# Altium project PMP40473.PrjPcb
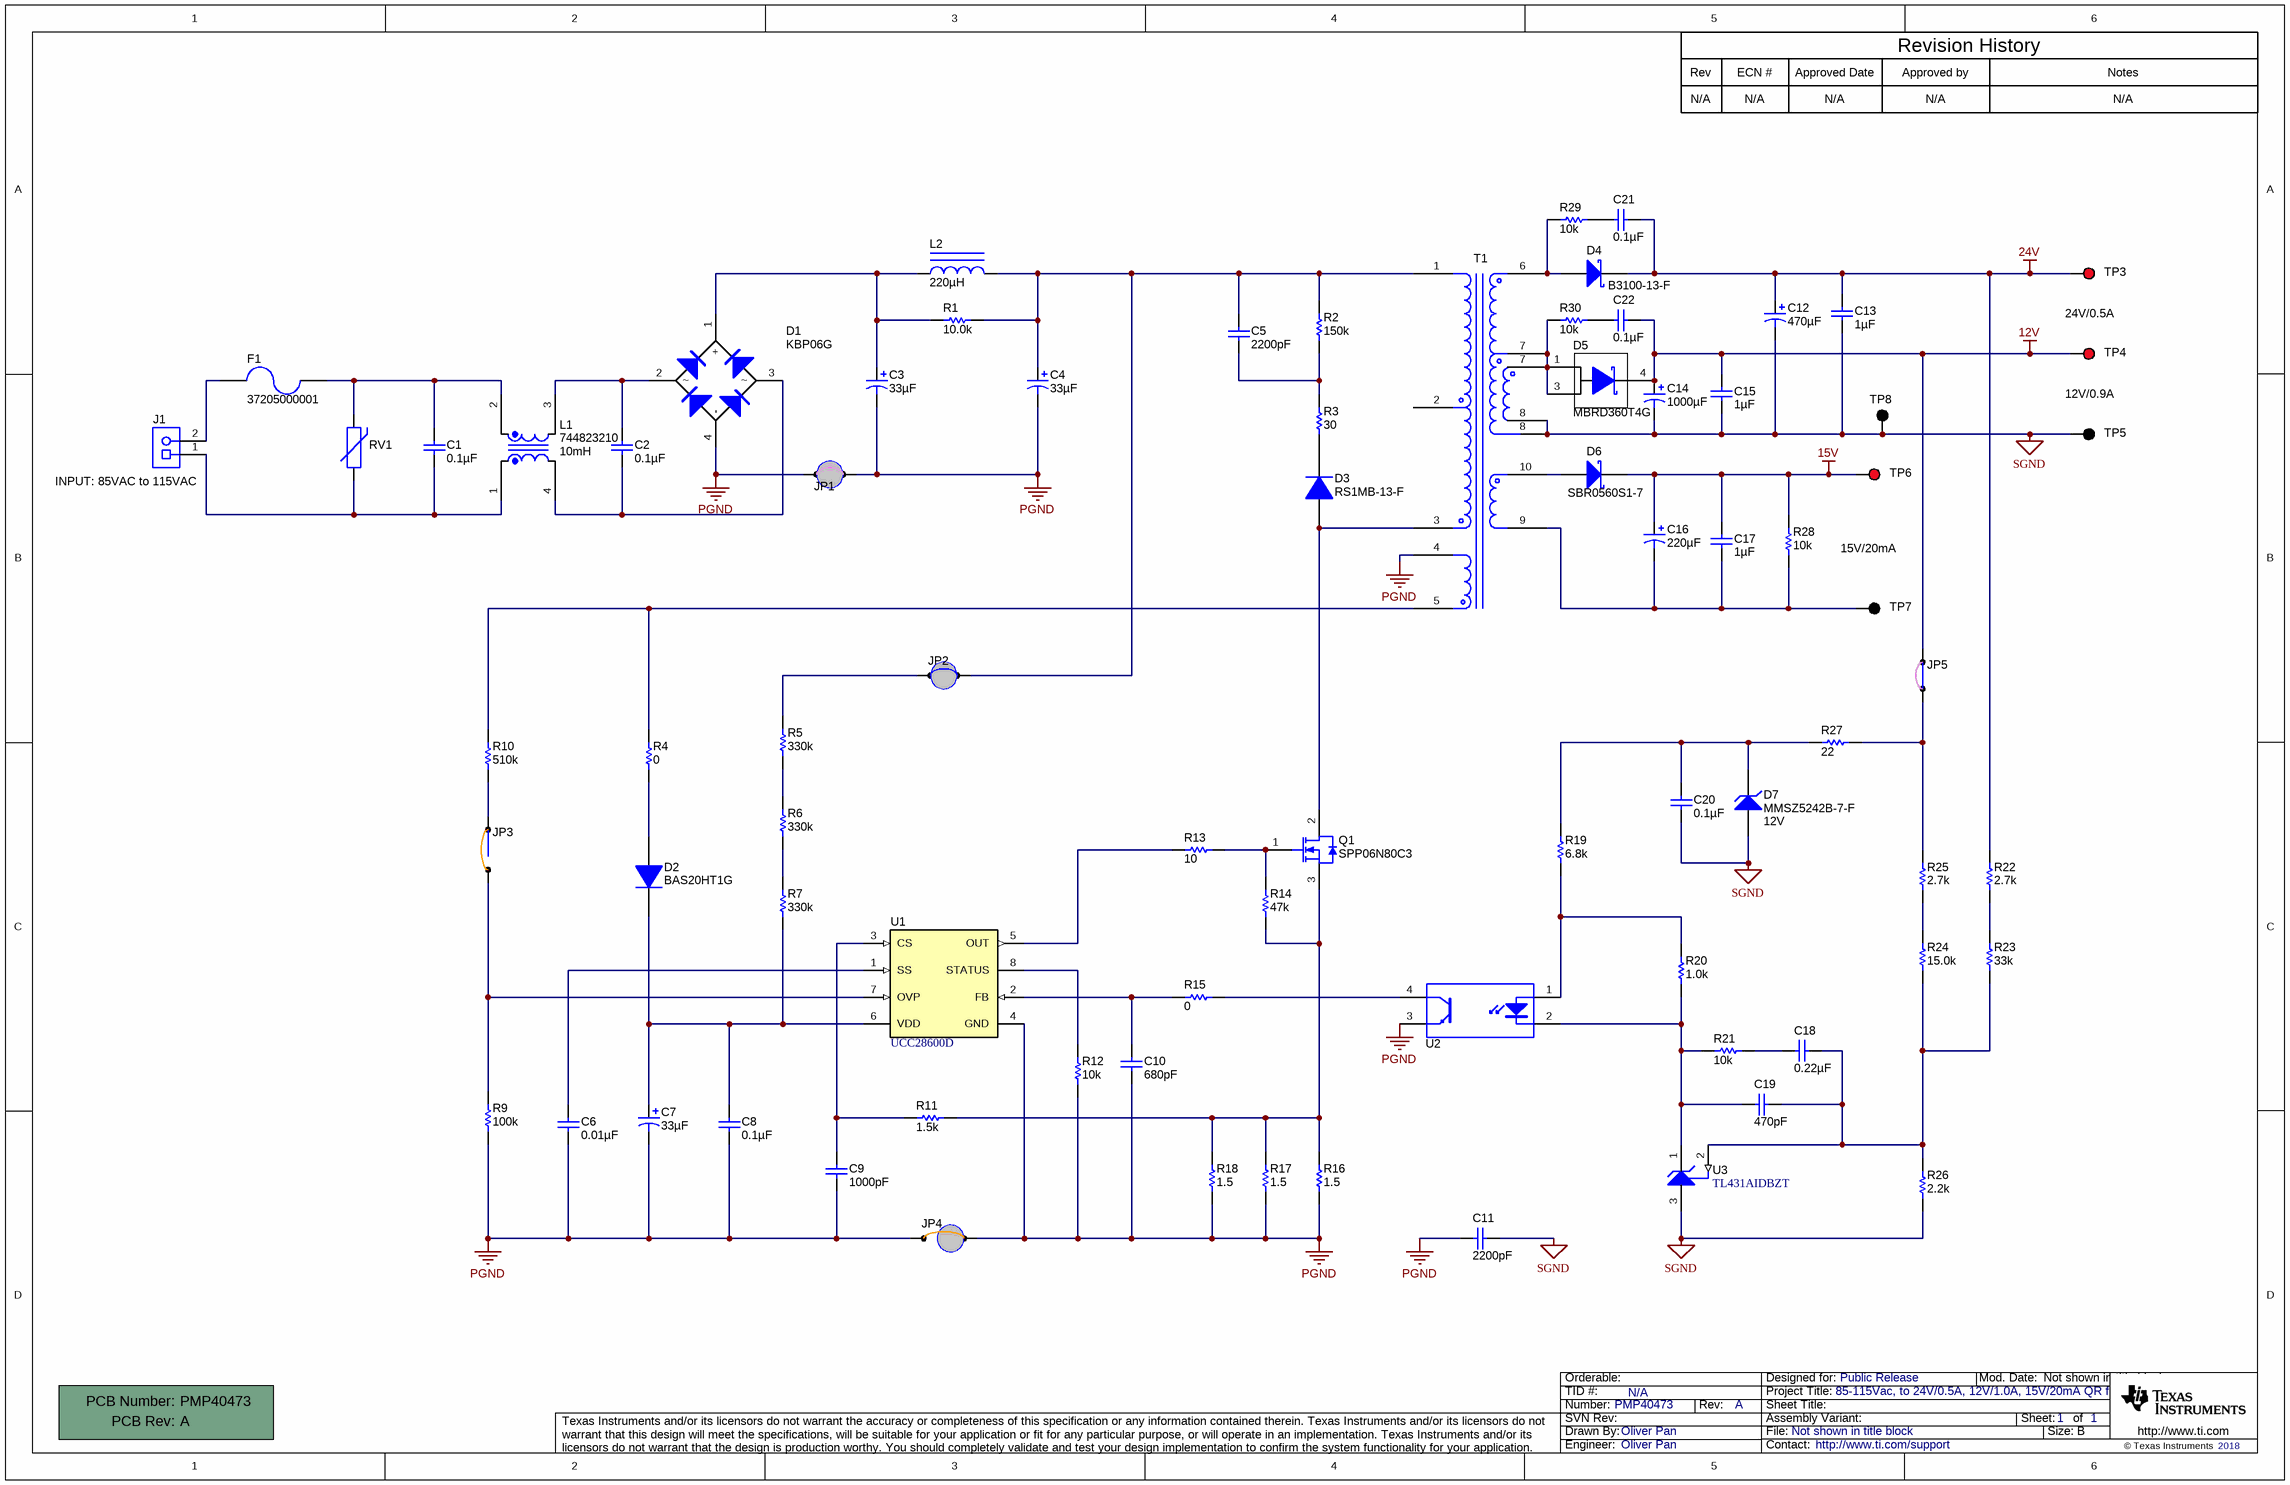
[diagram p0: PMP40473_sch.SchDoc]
CopyrightYear: 2018; PCB_Rev: A; PRJ_Customer: Public Release; PRJ_Engineer: Oliver Pan; PRJ_Number: PMP40473; PRJ_Title: 85-115Vac, to 24V/0.5A, 12V/1.0A, 15V/20mA QR flyback; SCH_Rev: A; TechSupport: http://www.ti.com/support; TID: N/A
1 sheet, 80 parts. Net scope: global (net labels, ports and power ports of the same name join across sheets).
Board file: PMP40473_pcb.PcbDoc

## Sheet PMP40473_sch.SchDoc
size 431 x 279 mm; Date: Not shown in title block; ApprovedBy: Not shown in title block; CheckedBy: Not shown in title block; Author: Not shown in title block; CompanyName: Not shown in title block; DrawnBy: Oliver Pan; Engineer: Not shown in title block; Organization: Not shown in title block; Address1: Not shown in title block; Address2: Not shown in title block; Address3: Not shown in title block; Address4: Not shown in title block; DocumentNumber: 1; Revision: Use project parameter SCH_Rev; SheetNumber: 1; SheetTotal: 1; PageSetup: Record=PageOptions¦CenterHorizontal=True¦CenterVertical=True¦PrintScale=1.00¦XCorrection=1.00¦YCorrection=1.00¦PrintKind=0¦BorderSize=5000000¦LeftOffset=0¦BottomOffset=0¦Orientation=2¦PaperLength=1000¦PaperWidth=1000¦Scale=100¦PaperSource=15¦PrintQuality=600¦MediaType=1¦DitherType=10¦PaperKind=Letter¦PrintScaleMode=1

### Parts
!PCB?  Printed Circuit Board  (value not drawn)  (mechanical)
C1  ValueDisplayed: 0.1µF  [WCAP-FTX2_1800x600x1200]  (hidden comment: 890324025017)
C2  ValueDisplayed: 0.1µF  [WCAP-FTX2_1800x600x1200]  (hidden comment: 890324025017)
C3  ValueDisplayed: 33µF  [KL_1000x2000]  (hidden comment: EKXG201ELL330MJ20S)
C4  ValueDisplayed: 33µF  [KL_1000x2000]  (hidden comment: EKXG201ELL330MJ20S)
C5  ValueDisplayed: 2200pF  [1206]  (hidden comment: GRM31BR72J222KW01L)
C6  ValueDisplayed: 0.01µF  [0805_HV]  (hidden comment: CC0805KRX7R9BB103)
C7  ValueDisplayed: 33µF  [Rubycon_500x1100]  (hidden comment: 35YXH33MEFC5X11)
C8  ValueDisplayed: 0.1µF  [0805_HV]  (hidden comment: C0805C104K5RACTU)
C9  ValueDisplayed: 1000pF  [0805_HV]  (hidden comment: GRM216R71E102KA01D)
C10  ValueDisplayed: 680pF  [0805_HV]  (hidden comment: GRM216R71E681KA01D)
C11  ValueDisplayed: 2200pF  [CAPRD1000W60D1000H1400]  (hidden comment: DE1E3KX222MA5BA01)
C12  ValueDisplayed: 470µF  [Chemi-Con_1000x2000]  (hidden comment: EKZE350ELL471MJ20S)
C13  ValueDisplayed: 1µF  [1206_180]  (hidden comment: C3216X7R1H105K160AB)
C14  ValueDisplayed: 1000µF  [Chemi-Con_1000x2000]  (hidden comment: EKMG250ELL102MJ20S)
C15  ValueDisplayed: 1µF  [1206]  (hidden comment: C1206C105K3RACTU)
C16  ValueDisplayed: 220µF  [Chemi-Con_800x1150]  (hidden comment: EKMG250ELL221MHB5D)
C17  ValueDisplayed: 1µF  [1206]  (hidden comment: C1206C105K3RACTU)
C18  ValueDisplayed: 0.22µF  [0805_HV]  (hidden comment: C2012X7R1H224K125AA)
C19  ValueDisplayed: 470pF  [0805_HV]  (hidden comment: 08055C471KAT2A)
C20  ValueDisplayed: 0.1µF  [0805_HV]  (hidden comment: GRM21BR71E104KA01L)
C21  ValueDisplayed: 0.1µF  [0805_HV]  (hidden comment: GRM21BR71E104KA01L)
C22  ValueDisplayed: 0.1µF  [0805_HV]  (hidden comment: GRM21BR71E104KA01L)
D1  KBP06G  [KBP]
D2  BAS20HT1G  [SOD-323]
D3  RS1MB-13-F  [SMB]
D4  B3100-13-F  [SMC]
D5  MBRD360T4G  [DPAK]
D6  SBR0560S1-7  [SOD-123]
D7  MMSZ5242B-7-F  value 12V  [SOD-123]
F1  37205000001  [FUSE_372]
J1  ED120/2DS  [On-Shore_ED120_2DS]  (value not drawn)
JP1  923345-20-C  [CONN_923345-07-C]  (value not drawn)
JP2  923345-20-C  [CONN_923345-06-C]  (value not drawn)
JP3  923345-20-C  [923345-03-C]  (value not drawn)
JP4  923345-20-C  [923345-03-C]  (value not drawn)
JP5  923345-20-C  [CONN_923345-07-C]  (value not drawn)
L1  744823210  ValueDisplayed: 10mH  [WE-CMB_M]
L2  ValueDisplayed: 220µH  [WE-TI_5075]  (hidden comment: Inductor Iron)
Q1  SPP06N80C3  [TO-220AB]
R1  ValueDisplayed: 10.0k  [0805_HV]  (hidden comment: Res2)
R2  ValueDisplayed: 150k  [CMF50]  (hidden comment: CMF50150K00FHEB)
R3  ValueDisplayed: 30  [1206]  (hidden comment: CRCW120630R0JNEA)
R4  ValueDisplayed: 0  [1206]  (hidden comment: RC1206JR-070RL)
R5  ValueDisplayed: 330k  [1206]  (hidden comment: CRCW1206330KJNEA)
R6  ValueDisplayed: 330k  [1206]  (hidden comment: CRCW1206330KJNEA)
R7  ValueDisplayed: 330k  [1206]  (hidden comment: CRCW1206330KJNEA)
R9  ValueDisplayed: 100k  [0805_HV]  (hidden comment: CRCW0805100KJNEA)
R10  ValueDisplayed: 510k  [0805_HV]  (hidden comment: CRCW0805510KJNEA)
R11  ValueDisplayed: 1.5k  [0805_HV]  (hidden comment: CRCW08051K50JNEA)
R12  ValueDisplayed: 10k  [0805_HV]  (hidden comment: CRCW080510K0JNEA)
R13  ValueDisplayed: 10  [0805_HV]  (hidden comment: CRCW080510R0JNEA)
R14  ValueDisplayed: 47k  [0805_HV]  (hidden comment: CRCW080547K0JNEA)
R15  ValueDisplayed: 0  [0805_HV]  (hidden comment: CRCW08050000Z0EA)
R16  ValueDisplayed: 1.5  [1206]  (hidden comment: CRCW12061R50JNEA)
R17  ValueDisplayed: 1.5  [1206]  (hidden comment: CRCW12061R50JNEA)
R18  ValueDisplayed: 1.5  [1206]  (hidden comment: CRCW12061R50JNEA)
R19  ValueDisplayed: 6.8k  [0805_HV]  (hidden comment: CRCW08056K80JNEA)
R20  ValueDisplayed: 1.0k  [0805_HV]  (hidden comment: CRCW08051K00JNEA)
R21  ValueDisplayed: 10k  [0805_HV]  (hidden comment: CRCW080510K0JNEA)
R22  ValueDisplayed: 2.7k  [0805_HV]  (hidden comment: CRCW08052K70JNEA)
R23  ValueDisplayed: 33k  [0805_HV]  (hidden comment: CRCW080533K0JNEA)
R24  ValueDisplayed: 15.0k  [0805_HV]  (hidden comment: CRCW080515K0FKEA)
R25  ValueDisplayed: 2.7k  [0805_HV]  (hidden comment: CRCW08052K70JNEA)
R26  ValueDisplayed: 2.2k  [0805_HV]  (hidden comment: CRCW08052K20JNEA)
R27  ValueDisplayed: 22  [1206]  (hidden comment: CRCW120622R0JNEA)
R28  ValueDisplayed: 10k  [1206]  (hidden comment: CRCW120610K0JNEA)
R29  ValueDisplayed: 10k  [1206]  (hidden comment: CRCW120610K0JNEA)
R30  ValueDisplayed: 10k  [1206]  (hidden comment: CRCW120610K0JNEA)
RV1  S10K275E2  [VAR_S10K275E2]  (value not drawn)
T1  750344218  [EE25-13-7_2607]  (value not drawn)
TP3  5010  [Keystone5010]  (value not drawn)
TP4  5010  [Keystone5010]  (value not drawn)
TP5  5011  [Keystone5011]  (value not drawn)
TP6  5010  [Keystone5010]  (value not drawn)
TP7  5011  [Keystone5011]  (value not drawn)
TP8  5011  [Keystone5011]  (value not drawn)
U1  UCC28600D  [D0008A_N]
U2  FOD817A  [DIP-4]  (value not drawn)
U3  TL431AIDBZT  [DBZ0003A_N]

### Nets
12V: C14.1(+) C15.1 C22.2 D5.4(K) JP5.2 TP4.1
15V: C16.1(+) C17.1 D6.1(K) R28.2 TP6.1
24V: C12.1(+) C13.1 C21.2 D4.1(K) R22.2 TP3.1
PGND: C3.2(-) C4.2(-) C6.1 C7.2(-) C8.2 C9.2 C10.2 C11.1 D1.4(-) JP1.1 JP1.2 JP4.1 JP4.2 R9.1 R12.1 R16.1 R17.1 R18.1 T1.4 U1.4(GND) U2.3(E)
SGND: C11.2 C12.2(-) C13.2 C14.2(-) C15.2 C20.2 D7.2(A) R26.1 T1.8 TP5.1 TP8.1 U3.3(ANODE)
NetC1_1: C1.1 F1.2 L1.2 RV1.2
NetC1_2: C1.2 J1.1 L1.1 RV1.1
NetC2_1: C2.1 D1.2 L1.3
NetC2_2: C2.2 D1.3 L1.4
NetC3_1: C3.1(+) D1.1(+) L2.1 R1.1
NetC4_1: C4.1(+) C5.1 JP2.2 L2.2 R1.2 R2.2 T1.1
NetC5_2: C5.2 R2.1 R3.2
NetC6_2: C6.2 U1.1(SS)
NetC7_1: C7.1(+) C8.1 D2.1(K) R7.1 U1.6(VDD)
NetC9_1: C9.1 R11.1 U1.3(CS)
NetC10_1: C10.1 R15.2 U1.2(FB)
NetC16_2: C16.2(-) C17.2 R28.1 T1.9 TP7.1
NetC18_1: C18.1 C19.1 R23.1 R24.1 R26.2 U3.2(REF)
NetC18_2: C18.2 R21.1
NetC19_2: C19.2 R20.2 R21.2 U2.2(K) U3.1(CATHODE)
NetC20_1: C20.1 D7.1(K) R19.1 R27.2
NetC21_1: C21.1 R29.1
NetC22_1: C22.1 R30.1
NetD2_2: D2.2(A) R4.1
NetD3_1: D3.1(K) R3.1
NetD3_2: D3.2(A) Q1.2(D) T1.3
NetD4_2: D4.2(A) R29.2 T1.6
NetD5_1: D5.1(A) D5.3(A) R30.2 T1.7
NetD6_2: D6.2(A) T1.10
NetF1_1: F1.1 J1.2
NetJP2_1: JP2.1 R5.2
NetJP3_1: JP3.1 R9.2 U1.7(OVP)
NetJP3_2: JP3.2 R10.1
NetJP5_1: JP5.1 R25.2 R27.1
NetQ1_1: Q1.1(G) R13.1 R14.2
NetQ1_3: Q1.3(S) R11.2 R14.1 R16.2 R17.2 R18.2
NetR4_2: R4.2 R10.2 T1.5
NetR5_1: R5.1 R6.2
NetR6_1: R6.1 R7.2
NetR12_2: R12.2 U1.8(STATUS)
NetR13_2: R13.2 U1.5(OUT)
NetR15_1: R15.1 U2.4(C)
NetR19_2: R19.2 R20.1 U2.1(A)
NetR22_1: R22.1 R23.2
NetR24_2: R24.2 R25.1

Not connected (* = marked no-connect by the designer): T1 2

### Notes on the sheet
- Rev
- N/A
- ECN #
- Approved Date
- Approved by
- Revision History
- Notes
- 24V/0.5A
- 12V/0.9A
- (near J1) INPUT: 85VAC to 115VAC
- 15V/20mA

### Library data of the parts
!PCB? = PCB: Manufacturer: Any; PartNumber: PMP40473; SymbolCreator: a0412235
C1 C2 = 890324025017: CAP, Film, 0.1 µF, X2 275 VAC, +/- 10%, TH; Manufacturer: Wurth Elektronik; Polarized: N; CompType: Capacitor; Value: 0.1uF; U/M: EA; Cap_F: 0.0000001; Tolerance_%: 10; TaMin_C: -40; TaMax_C: 105; Cap_Case: 18x6x12mm; AEC Category: Q200; Green_Lifecycle: Not Set; Green_REACh: Incomplete; VAC_X: 275
C3 C4 = EKXG401EC3330ML20S: CAP, AL, 33 µF, 400 V, +/- 20%, TH; Manufacturer: Chemi-Con; Polarized: Y; CompType: Capacitor; Value: 33uF; U/M: EA; Cap_F: 0.000033; Tolerance_%: 20; VDC_V: 200; Value2: 200V; IRMS_A: 0.26; TaMin_C: -40; TaMax_C: 105; Cap_Case: 10x20mm; SizeAreaWB_mm2: 324; SizeArea_mm2: 256; SizeX_mm: 10; SizeZ_mm: 21.5; AEC Category: Q200; AEC Qualified: N
C5 = GRM31BR72J222KW01L: CAP, CERM, 2200 pF, 630 V,+/- 10%, X7R, 1206; Manufacturer: MuRata; Polarized: N; CompType: Capacitor; Value: 2200pF; U/M: EA; Cap_F: 0.0000000022; Tolerance_%: 10; VDC_V: 630; Value2: 630V; TaMin_C: -55; TaMax_C: 125; SizeArea_mm2: 5.12; SizeAreaWB_mm2: 10.92; SizeX_mm: 3.2; SizeY_mm: 1.6; SizeZ_mm: 1.35; AEC Category: Q200; Green_Lifecycle: Not Set; Green_REACh: Incomplete
C6 = CC0805KRX7R9BB103: CAP, CERM, 0.01 µF, 50 V,+/- 10%, X7R, 0805; Manufacturer: Yageo America; Polarized: N; CompType: Capacitor; Value: 0.01uF; U/M: EA; Cap_F: 0.00000001; Tolerance_%: 10; VDC_V: 50; Value2: 50V; TaMin_C: -55; TaMax_C: 125; Cap_Case: 0805; SizeArea_mm2: 2.5; SizeAreaWB_mm2: 6.75; SizeX_mm: 2; SizeY_mm: 1.25; SizeZ_mm: 1.45; AEC Category: Q200; Green_Lifecycle: Active; Green_REACh: Passed
C7 = 35YXH33MEFC5X11: CAP, AL, 33 µF, 35 V, +/- 20%, TH; Manufacturer: Rubycon; Polarized: Y; CompType: Capacitor; Value: 33uF; U/M: EA; Cap_F: 0.000033; Tolerance_%: 20; VDC_V: 35; Value2: 35V; IRMS_A: 0.21; TaMin_C: -40; TaMax_C: 105; Cap_Case: 5x11mm; SizeAreaWB_mm2: 49; SizeArea_mm2: 25; SizeX_mm: 5; SizeZ_mm: 12.5; AEC Category: Q200; AEC Qualified: N
C8 = C0805C104K5RACTU: CAP, CERM, 0.1 µF, 50 V,+/- 10%, X7R, 0805; Manufacturer: Kemet; Polarized: N; CompType: Capacitor; Value: 0.1uF; U/M: EA; Cap_F: 0.0000001; Tolerance_%: 10; ESR_ohm: 0.064; Value1: 0.064 ohm; VDC_V: 50; Value2: 50V; IRMS_A: 1.64; TaMin_C: -55; TaMax_C: 125; Cap_Case: 0805; SizeArea_mm2: 2.5; SizeAreaWB_mm2: 6.75; SizeX_mm: 2; SizeY_mm: 1.25; SizeZ_mm: 1.45; AEC Category: Q200; Green_Lifecycle: Active; Green_REACh: Passed
C9 = GRM216R71E102KA01D: CAP, CERM, 1000 pF, 25 V,+/- 10%, X7R, 0805; Manufacturer: MuRata; Polarized: N; CompType: Capacitor; Value: 1000pF; U/M: EA; Cap_F: 0.000000001; Tolerance_%: 10; VDC_V: 25; Value2: 25V; TaMin_C: -55; TaMax_C: 125; Cap_Case: 0805; SizeArea_mm2: 2.5; SizeAreaWB_mm2: 6.75; SizeX_mm: 2; SizeY_mm: 1.25; SizeZ_mm: 1.45; AEC Category: Q200; Green_Lifecycle: Active; Green_REACh: Passed
C10 = GRM216R71E681KA01D: CAP, CERM, 680 pF, 25 V,+/- 10%, X7R, 0805; Manufacturer: MuRata; Polarized: N; CompType: Capacitor; Value: 680pF; U/M: EA; Cap_F: 0.00000000068; Tolerance_%: 10; VDC_V: 25; Value2: 25V; TaMin_C: -55; TaMax_C: 125; Cap_Case: 0805; SizeArea_mm2: 2.5; SizeAreaWB_mm2: 6.75; SizeX_mm: 2; SizeY_mm: 1.25; SizeZ_mm: 1.45; AEC Category: Q200
C11 = DE1E3KX222MA5BA01: CAP, CERM, 2200 pF, 250 V, +/- 20%, E, Disc 10x8mm; Manufacturer: MuRata; Polarized: N; CompType: Capacitor; Value: 2200pF; U/M: EA; Cap_F: 0.0000000022; Tolerance_%: 20; Value1: Unknown; VDC_V: 250; Value2: 250V; TaMin_C: -25; TaMax_C: 85; SizeArea_mm2: 80; SizeAreaWB_mm2: 120; SizeX_mm: 10; SizeY_mm: 8; SizeZ_mm: 14; AEC Category: Q200
C12 = EKZE350ELL471MJ20S: CAP, AL, 470 µF, 35 V, +/- 20%, TH; Manufacturer: Chemi-Con; Polarized: Y; CompType: Capacitor; Value: 470uF; U/M: EA; Cap_F: 0.00047; Tolerance_%: 20; VDC_V: 35; Value2: 35V; IRMS_A: 1.82; TaMin_C: -40; TaMax_C: 105; Cap_Case: 10x20; SizeAreaWB_mm2: 144; SizeArea_mm2: 100; SizeX_mm: 10; SizeZ_mm: 21.5; AEC Category: Q200; AEC Qualified: N
C13 = C3216X7R1H105K160AB: CAP, CERM, 1 µF, 50 V,+/- 10%, X7R, 1206; Manufacturer: TDK; Polarized: N; CompType: Capacitor; Value: 1uF; U/M: EA; Cap_F: 0.000001; Tolerance_%: 10; ESR_ohm: 0.009289; Value1: 0.009289 ohm; VDC_V: 50; Value2: 50V; IRMS_A: 2.38446; TaMin_C: -55; TaMax_C: 125; Cap_Case: 1206; SizeArea_mm2: 5.12; SizeAreaWB_mm2: 10.92; SizeX_mm: 3.2; SizeY_mm: 1.6; SizeZ_mm: 1.8; AEC Category: Q200; Green_Lifecycle: NRND; Green_REACh: Passed
C14 = EKMG250ELL102MJ20S: CAP, AL, 1000 µF, 25 V, +/- 20%, TH; Manufacturer: Chemi-Con; Polarized: Y; CompType: Capacitor; Value: 1000uF; U/M: EA; Cap_F: 0.001; Tolerance_%: 20; VDC_V: 25; Value2: 25V; IRMS_A: 0.68; TaMin_C: -55; TaMax_C: 105; Cap_Case: 10x20mm; SizeAreaWB_mm2: 144; SizeArea_mm2: 100; SizeX_mm: 10; SizeZ_mm: 21.5; AEC Category: Q200; AEC Qualified: N
C15 C17 = C1206C105K3RACTU: CAP, CERM, 1 µF, 25 V,+/- 10%, X7R, 1206; Manufacturer: Kemet; Polarized: N; CompType: Capacitor; Value: 1uF; U/M: EA; Cap_F: 0.000001; Tolerance_%: 10; ESR_ohm: 0.011; Value1: 0.011 ohm; VDC_V: 25; Value2: 25V; IRMS_A: 3.55; TaMin_C: -55; TaMax_C: 125; SizeArea_mm2: 5.12; SizeAreaWB_mm2: 10.92; SizeX_mm: 3.2; SizeY_mm: 1.6; SizeZ_mm: 1.35; AEC Category: Q200; Green_Lifecycle: Active; Green_REACh: Passed
C16 = EKMG250ELL221MHB5D: CAP, AL, 220 µF, 25 V, +/- 20%, TH; Manufacturer: Chemi-Con; Polarized: Y; CompType: Capacitor; Value: 220uF; U/M: EA; Cap_F: 0.00022; Tolerance_%: 20; VDC_V: 25; Value2: 25V; IRMS_A: 0.23; TaMin_C: -55; TaMax_C: 105; Cap_Case: 8x11.5mm; SizeAreaWB_mm2: 100; SizeArea_mm2: 64; SizeX_mm: 8; SizeZ_mm: 13; AEC Category: Q200; AEC Qualified: N
C18 = C2012X7R1H224K125AA: CAP, CERM, 0.22 µF, 50 V,+/- 10%, X7R, 0805; Manufacturer: TDK; Polarized: N; CompType: Capacitor; Value: 0.22uF; U/M: EA; Cap_F: 0.00000022; Tolerance_%: 10; ESR_ohm: 0.016949; Value1: 0.016949 ohm; VDC_V: 50; Value2: 50V; IRMS_A: 1.59611; TaMin_C: -55; TaMax_C: 125; Cap_Case: 0805; SizeArea_mm2: 2.5; SizeAreaWB_mm2: 6.75; SizeX_mm: 2; SizeY_mm: 1.25; SizeZ_mm: 1.45; AEC Category: Q200; Green_Lifecycle: Active; Green_REACh: Passed
C19 = 08055C471KAT2A: CAP, CERM, 470 pF, 50 V,+/- 10%, X7R, 0805; Manufacturer: AVX; Polarized: N; CompType: Capacitor; Value: 470pF; U/M: EA; Cap_F: 0.00000000047; Tolerance_%: 10; ESR_ohm: 0.454; Value1: 0.454 ohm; VDC_V: 50; Value2: 50V; TaMin_C: -55; TaMax_C: 125; Cap_Case: 0805; SizeArea_mm2: 2.5; SizeAreaWB_mm2: 6.75; SizeX_mm: 2; SizeY_mm: 1.25; SizeZ_mm: 1.45; AEC Category: Q200; Green_Lifecycle: Not Set; Green_REACh: Incomplete
C20-C22 = GRM21BR71E104KA01L: CAP, CERM, 0.1 µF, 25 V,+/- 10%, X7R, 0805; Manufacturer: MuRata; Polarized: N; CompType: Capacitor; Value: 0.1uF; U/M: EA; Cap_F: 0.0000001; Tolerance_%: 10; VDC_V: 25; Value2: 25V; TaMin_C: -55; TaMax_C: 125; Cap_Case: 0805; SizeArea_mm2: 2.5; SizeAreaWB_mm2: 6.75; SizeX_mm: 2; SizeY_mm: 1.25; SizeZ_mm: 1.45; AEC Category: Q200; Green_Lifecycle: Active; Green_REACh: Passed
D1 = KBP06G: Diode, Switching-Bridge, 600 V, 1.5 A, TH; Manufacturer: Diodes Inc.; U/M: EA; Vf_V: 1.1; Value: 600V; Value1: 1.5A; Value2: 1.1V; Io_A: 1.5; Vr_V: 600; TJmax_C: 150; RJC_CperW: 18; SizeAreaWB_mm2: 79.75; SizeArea_mm2: 43.75; SizeX_mm: 12.5; SizeY_mm: 3.5; SizeZ_mm: 12.69; AEC Category: Q101; Green_Lifecycle: Not Set; Green_REACh: Incomplete
D2 = BAS20HT1G: Diode, Switching, 200 V, 0.2 A, AEC-Q101, SOD-323; Manufacturer: ON Semiconductor; U/M: EA; Vf_V: 1.25; Value: 200V; Value1: 0.2A; Value2: 1.25V; Io_A: 0.2; Vr_V: 200; TJmax_C: 150; SizeAreaWB_mm2: 8.695; SizeArea_mm2: 3.645; SizeX_mm: 2.7; SizeY_mm: 1.35; SizeZ_mm: 1; AEC Category: Q101; AEC Qualified: Y
D3 = RS1MB-13-F: Diode, P-N, 1000 V, 1 A, SMB; Manufacturer: Diodes Inc.; U/M: EA; Vf_V: 1.3; Value: 1000V; Value1: 1A; Value2: 1.3V; Io_A: 1; Vr_V: 1000; TJmax_C: 150; RJC_CperW: 20; SizeAreaWB_mm2: 44.156; SizeArea_mm2: 21.336; SizeX_mm: 5.6; SizeY_mm: 3.81; SizeZ_mm: 2.6; AEC Category: Q101; Green_Lifecycle: Active; Green_REACh: Passed
D4 = B3100-13-F: Diode, Schottky, 100 V, 3 A, SMC; Manufacturer: Diodes Inc.; U/M: EA; Vf_V: 0.79; Value: 100V; Value1: 3A; Value2: 0.79V; Io_A: 3; Vr_V: 100; TJmax_C: 125; RJC_CperW: 10; SizeAreaWB_mm2: 83.2686; SizeArea_mm2: 50.5686; SizeX_mm: 8.13; SizeY_mm: 6.22; SizeZ_mm: 2.6; AEC Category: Q101; Green_Lifecycle: Active; Green_REACh: Passed
D5 = MBRD360T4G: Diode, Schottky, 60 V, 3 A, DPAK; Manufacturer: ON Semiconductor; U/M: EA; Vf_V: 0.6; Value: 60V; Value1: 3A; Value2: 0.6V; Io_A: 3; Vr_V: 60; TJmax_C: 150; RJC_CperW: 6; SizeAreaWB_mm2: 101.7114; SizeArea_mm2: 64.8114; SizeX_mm: 9.91; SizeY_mm: 6.54; SizeZ_mm: 2.29; AEC Category: Q101; Green_Lifecycle: Not Set; Green_REACh: Incomplete
D6 = SBR0560S1-7: Diode, Schottky, 60 V, 0.5 A, SOD-123; Manufacturer: Diodes Inc.; U/M: EA; Vf_V: 0.5; Value: 60V; Value1: 0.5A; Value2: 0.5V; Vr_V: 60; TJmax_C: 150; SizeAreaWB_mm2: 13.095; SizeArea_mm2: 6.545; SizeX_mm: 3.85; SizeY_mm: 1.7; SizeZ_mm: 1.35; AEC Category: Q101; AEC Qualified: N; Green_Lifecycle: Not Set; Green_REACh: Incomplete
D7 = MMSZ5242B-7-F: Diode, Zener, 12 V, 500 mW, SOD-123; Manufacturer: Diodes Inc.; U/M: EA; Value1: 0.5W; SizeAreaWB_mm2: 13.095; SizeArea_mm2: 6.545; SizeX_mm: 3.85; SizeY_mm: 1.7; SizeZ_mm: 1.35; AEC Category: Q101; SymbolCreator: a0412235; Power_W: 0.5; Vz_V: 12; RJA_CperW: 350
F1 = 37205000001: Fuse, 0.5 A, 250VAC/VDC, TH; Manufacturer: Littelfuse; VDC_V: 250; Irating_A: 0.5
J1 = CMP-0074910-1: Terminal Block, 5.08 mm, 2x1, Brass, TH; Manufacturer: On-Shore Technology; Cert_VDE: Y; CNHeader: False; Current_A: 15A; Green_Lifecycle: Not Set; Shrouded: N; Gender: Female; Green_REACh: Incomplete; Voltage_V: 300V; Row_Count: 1; Pitch_mm: 5.08; CT: True
JP1 JP5 = CMP-0074936-1: Jumper Wire, 700mil spacing, Violet, pkg of 150, TH; Manufacturer: 3M; CNHeader: False; Green_Lifecycle: Active; Green_REACh: Passed
JP2 = CMP-0074937-1: Jumper Wire, 600mil spacing, Blue, pkg of 150, TH; Manufacturer: 3M; CNHeader: False; Green_Lifecycle: Active; Green_REACh: Passed
JP3 JP4 = CMP-0055440-1: Jumper Wire, 300mil spacing, Orange, pkg of 200; Manufacturer: 3M; CNHeader: FALSE; Green_Lifecycle: Active; Green_REACh: Passed
L1 = 744823210: Coupled inductor, 10 mH, 2 A, 0.125 ohm, TH; Manufacturer: Wurth Elektronik; SymbolCreator: a0799628; SizeAreaWB_mm2: 513; SizeArea_mm2: 425; SizeX_mm: 25; SizeY_mm: 17; SizeZ_mm: 26.5; Value: 10mH; Ind_H: 10.0E-3; DCR_ohm: 0.125; AEC Category: Q200
L2 = 7447462221: Inductor, Unshielded Drum Core, Ferrite, 220 µH, 0.5 A, 0.96 ohm, TH; Manufacturer: Wurth Elektronik; Value: 220uH; Ind_H: 220.0E-6; Imax_A: 0.5; Irms: 0.5A @ 40C rise; Isat: 0.5A @ 10% inductance drop; DCR_ohm: 0.96; Value2: 0.5A; AEC Category: Q200
Q1 = SPP06N80C3: MOSFET, N-CH, 800 V, 6 A, TO-220AB; Manufacturer: Infineon Technologies; Alternate Manufacturer: None; U/M: EA; ChType: N; Value: 800V; VdsMax_V: 800; Value1: 0.9 ohm; Rdson45_ohm: 0.9; Value2: 41 nC; QgTyp_nC: 41; Vgs_V: 3.9; IdsMax_A: 6; SizeAreaWB_mm2: 79.3; SizeArea_mm2: 45.9; SizeX_mm: 10.2; SizeY_mm: 4.5; SizeZ_mm: 19.4; AEC Category: Q101; Green_Lifecycle: Not Set; Green_REACh: Incomplete
R1 = CRCW080510K0FKEA: RES, 10.0 k, 1%, 0.125 W, 0805; Manufacturer: Vishay-Dale; CompType: Resistor; Value: 10.0k; Res_ohm: 10000; Value_Code: 10k0; Tolerance_%: 1; Power_W: 0.125; Value2: 0.125W; VDC_V: 150; TempCo: 100 ppm/C; EIA_Code: E96; U/M: EA; AEC Category: Q200
R2 = CMF50150K00FHEB: RES, 150 k, 1%, 0.25 W, Axial; Manufacturer: Vishay-Dale; CompType: Resistor; Value: 150k; Res_ohm: 150000; Tolerance_%: 1; Power_W: 0.25; Value2: 0.25W; VDC_V: 200; TempCo: 50 ppm/C; EIA_Code: E96; U/M: EA; AEC Category: Q200
R3 = CRCW120630R0JNEA: RES, 30, 5%, 0.25 W, 1206; Manufacturer: Vishay-Dale; CompType: Resistor; Value: 30; Value_Code: 30R0; Tolerance_%: 5; Power_W: 0.25; Value2: 0.25W; VDC_V: 200; TempCo: 200 ppm/C; EIA_Code: E24; U/M: EA; SizeArea_mm2: 5.12; SizeX_mm: 3.2; SizeY_mm: 1.6; SizeZ_mm: 1.35; AEC Category: Q200
R4 = RC1206JR-070RL: RES, 0, 5%, 0.25 W, 1206; Manufacturer: Yageo America; CompType: Resistor; Value: 0; Value_Code: 0000; Tolerance_%: 5; Power_W: 0.25; Value2: 0.25W; VDC_V: 200; TempCo: 200 ppm/C; SizeArea_mm2: 5.12; SizeX_mm: 3.2; SizeY_mm: 1.6; SizeZ_mm: 1.35; EIA_Code: E24; U/M: EA; AEC Category: Q200; Green_Lifecycle: Active; Green_REACh: Passed
R5-R7 = CRCW1206330KJNEA: RES, 330 k, 5%, 0.25 W, 1206; Manufacturer: Vishay-Dale; CompType: Resistor; Value: 330k; Res_ohm: 330000; Tolerance_%: 5; Power_W: 0.25; Value2: 0.25W; VDC_V: 200; TempCo: 200 ppm/C; SizeArea_mm2: 5.12; SizeX_mm: 3.2; SizeY_mm: 1.6; SizeZ_mm: 1.35; EIA_Code: E24; U/M: EA; AEC Category: Q200
R9 = CRCW0805100KJNEA: RES, 100 k, 5%, 0.125 W, 0805; Manufacturer: Vishay-Dale; CompType: Resistor; Value: 100k; Res_ohm: 100000; Tolerance_%: 5; Power_W: 0.125; Value2: 0.125W; VDC_V: 150; TempCo: 200 ppm/C; SizeArea_mm2: 2.5; SizeX_mm: 2; SizeY_mm: 1.25; SizeZ_mm: 1.45; EIA_Code: E24; U/M: EA; AEC Category: Q200; Green_Lifecycle: Active; Green_REACh: Passed
R10 = CRCW0805510KJNEA: RES, 510 k, 5%, 0.125 W, 0805; Manufacturer: Vishay-Dale; CompType: Resistor; Value: 510k; Res_ohm: 510000; Tolerance_%: 5; Power_W: 0.125; Value2: 0.125W; VDC_V: 150; TempCo: 200 ppm/C; SizeArea_mm2: 2.5; SizeX_mm: 2; SizeY_mm: 1.25; SizeZ_mm: 1.45; EIA_Code: E24; U/M: EA; AEC Category: Q200; Green_Lifecycle: Active; Green_REACh: Passed
R11 = CRCW08051K50JNEA: RES, 1.5 k, 5%, 0.125 W, 0805; Manufacturer: Vishay-Dale; CompType: Resistor; Value: 1.5k; Res_ohm: 1500; Value_Code: 1k50; Tolerance_%: 5; Power_W: 0.125; Value2: 0.125W; VDC_V: 150; TempCo: 200 ppm/C; SizeArea_mm2: 2.5; SizeX_mm: 2; SizeY_mm: 1.25; SizeZ_mm: 1.45; EIA_Code: E24; U/M: EA; AEC Category: Q200
R12 R21 = CRCW080510K0JNEA: RES, 10 k, 5%, 0.125 W, 0805; Manufacturer: Vishay-Dale; CompType: Resistor; Value: 10k; Res_ohm: 10000; Value_Code: 10k0; Tolerance_%: 5; Power_W: 0.125; Value2: 0.125W; VDC_V: 150; TempCo: 200 ppm/C; SizeArea_mm2: 2.5; SizeX_mm: 2; SizeY_mm: 1.25; SizeZ_mm: 1.45; EIA_Code: E24; U/M: EA; AEC Category: Q200; Green_Lifecycle: Active; Green_REACh: Passed
R13 = CRCW080510R0JNEA: RES, 10, 5%, 0.125 W, 0805; Manufacturer: Vishay-Dale; CompType: Resistor; Value: 10; Value_Code: 10R0; Tolerance_%: 5; Power_W: 0.125; Value2: 0.125W; VDC_V: 150; TempCo: 200 ppm/C; SizeArea_mm2: 2.5; SizeX_mm: 2; SizeY_mm: 1.25; SizeZ_mm: 1.45; EIA_Code: E24; U/M: EA; AEC Category: Q200
R14 = CRCW080547K0JNEA: RES, 47 k, 5%, 0.125 W, 0805; Manufacturer: Vishay-Dale; CompType: Resistor; Value: 47k; Res_ohm: 47000; Value_Code: 47k0; Tolerance_%: 5; Power_W: 0.125; Value2: 0.125W; VDC_V: 150; TempCo: 200 ppm/C; SizeArea_mm2: 2.5; SizeX_mm: 2; SizeY_mm: 1.25; SizeZ_mm: 1.45; EIA_Code: E24; U/M: EA; AEC Category: Q200
R15 = CRCW08050000Z0EA: RES, 0, 5%, 0.125 W, 0805; Manufacturer: Vishay-Dale; CompType: Resistor; Value: 0; Value_Code: 0000; Tolerance_%: 5; Power_W: 0.125; Value2: 0.125W; VDC_V: 150; TempCo: 200 ppm/C; SizeArea_mm2: 2.5; SizeX_mm: 2; SizeY_mm: 1.25; SizeZ_mm: 1.45; EIA_Code: E24; U/M: EA; AEC Category: Q200; Green_Lifecycle: Active; Green_REACh: Passed
R16-R18 = CRCW12061R50JNEA: RES, 1.5, 5%, 0.25 W, 1206; Manufacturer: Vishay-Dale; CompType: Resistor; Value: 1.5; Value_Code: 1R50; Tolerance_%: 5; Power_W: 0.25; Value2: 0.25W; VDC_V: 200; TempCo: 200 ppm/C; SizeArea_mm2: 5.12; SizeX_mm: 3.2; SizeY_mm: 1.6; SizeZ_mm: 1.35; EIA_Code: E24; U/M: EA; AEC Category: Q200
R19 = CRCW08056K80JNEA: RES, 6.8 k, 5%, 0.125 W, 0805; Manufacturer: Vishay-Dale; CompType: Resistor; Value: 6.8k; Res_ohm: 6800; Value_Code: 6k80; Tolerance_%: 5; Power_W: 0.125; Value2: 0.125W; VDC_V: 150; TempCo: 200 ppm/C; SizeArea_mm2: 2.5; SizeX_mm: 2; SizeY_mm: 1.25; SizeZ_mm: 1.45; EIA_Code: E24; U/M: EA; AEC Category: Q200
R20 = CRCW08051K00JNEA: RES, 1.0 k, 5%, 0.125 W, 0805; Manufacturer: Vishay-Dale; CompType: Resistor; Value: 1.0k; Res_ohm: 1000; Value_Code: 1k00; Tolerance_%: 5; Power_W: 0.125; Value2: 0.125W; VDC_V: 150; TempCo: 200 ppm/C; SizeArea_mm2: 2.5; SizeX_mm: 2; SizeY_mm: 1.25; SizeZ_mm: 1.45; EIA_Code: E24; U/M: EA; AEC Category: Q200; Green_Lifecycle: Active; Green_REACh: Passed
R22 R25 = CRCW08052K70JNEA: RES, 2.7 k, 5%, 0.125 W, 0805; Manufacturer: Vishay-Dale; CompType: Resistor; Value: 2.7k; Res_ohm: 2700; Value_Code: 2k70; Tolerance_%: 5; Power_W: 0.125; Value2: 0.125W; VDC_V: 150; TempCo: 200 ppm/C; SizeArea_mm2: 2.5; SizeX_mm: 2; SizeY_mm: 1.25; SizeZ_mm: 1.45; EIA_Code: E24; U/M: EA; AEC Category: Q200
R23 = CRCW080533K0JNEA: RES, 33 k, 5%, 0.125 W, 0805; Manufacturer: Vishay-Dale; CompType: Resistor; Value: 33k; Res_ohm: 33000; Value_Code: 33k0; Tolerance_%: 5; Power_W: 0.125; Value2: 0.125W; VDC_V: 150; TempCo: 200 ppm/C; SizeArea_mm2: 2.5; SizeX_mm: 2; SizeY_mm: 1.25; SizeZ_mm: 1.45; EIA_Code: E24; U/M: EA; AEC Category: Q200
R24 = CRCW080515K0FKEA: RES, 15.0 k, 1%, 0.125 W, 0805; Manufacturer: Vishay-Dale; CompType: Resistor; Value: 15.0k; Res_ohm: 15000; Value_Code: 15k0; Tolerance_%: 1; Power_W: 0.125; Value2: 0.125W; VDC_V: 150; TempCo: 100 ppm/C; SizeArea_mm2: 2.5; SizeX_mm: 2; SizeY_mm: 1.25; SizeZ_mm: 1.45; EIA_Code: E96; U/M: EA; AEC Category: Q200; Green_Lifecycle: Active; Green_REACh: Passed
R26 = CRCW08052K20JNEA: RES, 2.2 k, 5%, 0.125 W, 0805; Manufacturer: Vishay-Dale; CompType: Resistor; Value: 2.2k; Res_ohm: 2200; Value_Code: 2k20; Tolerance_%: 5; Power_W: 0.125; Value2: 0.125W; VDC_V: 150; TempCo: 200 ppm/C; SizeArea_mm2: 2.5; SizeX_mm: 2; SizeY_mm: 1.25; SizeZ_mm: 1.45; EIA_Code: E24; U/M: EA; AEC Category: Q200
R27 = CRCW120622R0JNEA: RES, 22, 5%, 0.25 W, 1206; Manufacturer: Vishay-Dale; CompType: Resistor; Value: 22; Value_Code: 22R0; Tolerance_%: 5; Power_W: 0.25; Value2: 0.25W; VDC_V: 200; TempCo: 200 ppm/C; SizeArea_mm2: 5.12; SizeX_mm: 3.2; SizeY_mm: 1.6; SizeZ_mm: 1.35; EIA_Code: E24; U/M: EA; AEC Category: Q200
R28-R30 = CRCW120610K0JNEA: RES, 10 k, 5%, 0.25 W, 1206; Manufacturer: Vishay-Dale; CompType: Resistor; Value: 10k; Res_ohm: 10000; Value_Code: 10k0; Tolerance_%: 5; Power_W: 0.25; Value2: 0.25W; VDC_V: 200; TempCo: 200 ppm/C; SizeArea_mm2: 5.12; SizeX_mm: 3.2; SizeY_mm: 1.6; SizeZ_mm: 1.35; EIA_Code: E24; U/M: EA; AEC Category: Q200
RV1 = S10K275E2: Varistor 275V RMS 10MM Radial, TH; Manufacturer: TDK; SymbolCreator: a0412235; SizeAreaWB_mm2: 103.6; SizeArea_mm2: 64.8; SizeX_mm: 12; SizeY_mm: 5.4; SizeZ_mm: 14.5; Green_Lifecycle: Not Set; Green_REACh: Incomplete
T1 = EF25: Transformer, EF25, 420uH, 10-pins, TH; Manufacturer: Wurth
TP3 TP4 TP6 = 5010: Test Point, Multipurpose, Red, TH; Manufacturer: Keystone; CompType: Test Point Loop; ContactFinish: Silver; Green_Lifecycle: Active; Green_REACh: Passed
TP5 TP7 TP8 = 5011: Test Point, Multipurpose, Black, TH; Manufacturer: Keystone; CompType: Test Point Loop; ContactFinish: Silver; Green_Lifecycle: Active; Green_REACh: Passed
U1 = UCC28600D: Quasi-Resonant Flyback Green-Mode Controller with Current Control, 99 % Duty Cycle, -40 to +105 degC, 8-pin SOIC (D), Green (RoHS & no Sb/Br); Manufacturer: Texas Instruments; Alternate PartNumber: Equivalent; Duty Cycle(Max)(%): 99; Frequency(Max)(kHz): 130; Rating: Catalog; Regulated Outputs(#): 1; SubFamily: PWM Controller; UVLO Thresholds On/Off(V): 10.3/9.3
U2 = FOD817A: Optocoupler, 5 kV, 80-160% CTR, TH; Manufacturer: Fairchild Semiconductor; CTR (Min): 80%; CTR (Max): 160%; Voltage_Isolation_Vrms: 5000V; SizeAreaWB_mm2: 71.064; SizeArea_mm2: 40.304; SizeX_mm: 8.8; SizeY_mm: 4.58; SizeZ_mm: 5
U3 = TL431AIDBZT: Adjustable Precision Shunt Regulator, 34 ppm / degC, 100 mA, -40 to 85 degC, 3-pin SOT-23 (DBZ), Green (RoHS & no Sb/Br); Manufacturer: Texas Instruments; Alternate PartNumber: Equivalent; Initial Accuracy @ 25/deg C(%): 1; Iout/Iz(Max)(mA): 100; Min Iz for Regulation(uA): 600; Rating: Catalog; SubFamily: Shunt Voltage Reference; Temp Coeff(Max)(ppm/ degree C): 92; Temp Coeff(Typ)(ppm/ degree C): 34; VO Adj(Max)(V): 36; VO Adj(Min)(V): 2.495

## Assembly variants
001: not fitted C19; alternate parts R10 -> CRCW0805100KJNEA, R9 -> CRCW080530K0JNEA, R11 -> CRCW08051K80JNEA, C10 -> C0805C391K5RACTU
002: not fitted C19 C21 C22 R12 R29 R30; alternate parts R10 -> CRCW0805100KJNEA, R9 -> CRCW080530K0JNEA, R11 -> CRCW08051K80JNEA, C10 -> C0805C391K5RACTU, C5 -> GRM31BR72J102KW01L, C16 -> EKMG250ELL102MJ20S, R3 -> CRCW12064R70JNEA, R19 -> CRCW08051K00JNEA, R13 -> RC0805JR-072R2L, R4 -> CRCW12064R70JNEA, R2 -> PR02000201003JR500, C6 -> 08055C333KAT2A, R28 -> CRCW120633K0JNEA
